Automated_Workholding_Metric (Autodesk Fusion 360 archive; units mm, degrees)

design "Automated_Workholding_Start_Metric" references "Broached Hexagon Socket Head Cap Screw ANSI B18.3.1M - M12x1.75 x 60 Steel Grade 2 Plain", "autodesk 5ax table ac head xyz"
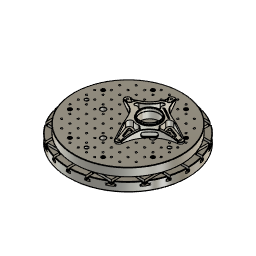
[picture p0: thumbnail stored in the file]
part number: Configuration 1
description: Part Number
part number: Hub
part number: Hub Stock
parameter "d185" = 0
base_feature "Base Feature1" bodies "c_axis_table"
sketch "Sketch1" plane through (0, 0, -15.5) normal (0, 0, -1) x axis (1, 0, 0)
  line L1 (93, 7) -> (59.5903, 7)
  line L2 (93, 93) -> (93, 7)
  line L3 (7, 93) -> (93, 93)
  line L4 (7, 59.5903) -> (7, 93)
  line L5 (12, 88) -> (12, 58.7878)
  line L6 (88, 88) -> (12, 88)
  line L7 (88, 12) -> (88, 88)
  line L8 (58.7878, 12) -> (88, 12)
  line L9 (293, -93) -> (293, -107)
  line L10 (256.1738, -100) -> (293, -100)
  arc A1 centre (0, 0) radius 60 clockwise from (58.7878, 12) to (59.5903, 7)
  arc A2 centre (0, 0) radius 60 clockwise from (7, 59.5903) to (12, 58.7878)
  circle C1 centre (0, 0) radius 275
  point P14 (293, -107)
  point P16 (293, -107)
  point P15 (293, -93)
  point P17 (293, -93)
  point P18 (293, -100)
  point P19 (256.1738, -100)
  point P20 (256.1738, -100)
  concentric A1 C1
  coincident P14 P16
  coincident P15 P17
  midpoint L9 P18
  coincident C1 P19
  perpendicular L9 L10
  coincident P19 P20
  dimension "d1" diameter C1 = 550
  dimension "d181" alignAngle = 0
  dimension "d182" alignOffsetX = 0
  dimension "d183" alignOffsetY = 0
  dimension "d184" alignOffsetZ = 0
  dimension "d185" alignAngle = 0
  dimension "d186" alignOffsetX = 0
  dimension "d187" alignOffsetY = 0
  dimension "d188" alignOffsetZ = 0
  dimension "d189" alignAngle = 0
  dimension "d190" alignOffsetX = 0
  dimension "d191" alignOffsetY = 0
  dimension "d192" alignOffsetZ = 0
  dimension "d193" alignAngle = 0
  dimension "d194" alignOffsetX = 0
  dimension "d195" alignOffsetY = 0
  dimension "d196" alignOffsetZ = 0
  dimension "d197" alignAngle = 0
  dimension "d198" alignOffsetX = 0
  dimension "d199" alignOffsetY = 0
  dimension "d200" alignOffsetZ = 0
  dimension "d201" alignAngle = 0
  dimension "d202" alignOffsetX = 0
  dimension "d203" alignOffsetY = 0
  dimension "d204" alignOffsetZ = 0
  dimension "d205" alignAngle = 0
  dimension "d206" alignOffsetX = 0
  dimension "d207" alignOffsetY = 0
  dimension "d208" alignOffsetZ = 0
  dimension "d209" alignAngle = 0
  dimension "d210" alignOffsetX = 0
  dimension "d211" alignOffsetY = 0
  dimension "d212" alignOffsetZ = 0
as_built_joint "As-built1"
work_plane "WorkPlane1"
sketch "Sketch1" plane through (256.1738, 100, -15.5) normal (-1, 0, 0) x axis (0, -1, 0)
  line L1 (0, 5) -> (0, -9)
  line L2 (7, 5) -> (0, 5)
  line L3 (11, -9) -> (0, -9)
  line L4 (11, 0) -> (11, -9)
  line L5 (7, 0) -> (11, 0)
  line L6 (7, 5) -> (7, 0)
  line L7 (-7, 5) -> (0, 5)
  line L8 (-7, 5) -> (-7, 0)
  line L9 (-7, 0) -> (-11, 0)
  line L10 (-11, 0) -> (-11, -9)
  line L11 (-11, -9) -> (0, -9)
  point P5 (0, 0)
  point P9 (7, 0)
  point P2 (0, -9)
  point P15 (0, -9)
  point P3 (0, 5)
  point P10 (0, 5)
  point P4 (7, 5)
  point P11 (-7, 5)
  point P6 (11, -9)
  point P14 (-11, -9)
  point P7 (11, 0)
  point P13 (-11, 0)
  point P8 (7, 0)
  point P12 (-7, 0)
  vertical L1
  perpendicular L1 L2
  coincident L1 P5
  perpendicular L1 L3
  perpendicular L3 L4
  perpendicular L1 L5
  perpendicular L2 L6
  coincident L5 P9
  symmetric P2 L1 P15
  symmetric P3 L1 P10
  symmetric L1 P4 P11
  symmetric L1 P6 P14
  symmetric L1 P7 P13
  symmetric L1 P8 P12
  dimension "d4" distance L1 P4 = 7 (= "( 14 / 2 ) * 1 mm")
  dimension "d5" distance P2 P3 = 14
  dimension "d6" distance P2 P6 = 11 (= "( 22 / 2 ) * 1 mm")
  dimension "d7" distance P6 P7 = 9
extrude "Extrude1" new body sketch "Sketch1" profile of L2 L3 L4 L5 L6 L7 L8 L9 L10 L11 distance 29
hole "Hole1" HoleDiameter 10.274 TipAngle 118
chamfer "Chamfer1" distance 3 distance 1
as_built_joint "As-built1"
mirror_component "MirrorComponent1"
derived_instance "DerivedInstance1"
as_built_joint "As-built2"
step "00000000-0000-0000-0000-000000000000" TotalAngle 360
work_plane "WorkPlane1" AlongDistance 20
sketch "Sketch1" plane through (0, 0, 20) normal (0, 0, 1) x axis (1, 0, 0)
  line L1 (0, 66.3083) -> (0, 0)
  circle C1 centre (100, -256.1738) radius 5.1368
  circle C2 centre (256.1738, -100) radius 5.1368
  circle C3 centre (256.1738, 100) radius 5.1368
  circle C4 centre (100, 256.1738) radius 5.1368
  circle C5 centre (-100, 256.1738) radius 5.1368
  circle C6 centre (-256.1738, 100) radius 5.1368
  circle C7 centre (-256.1738, -100) radius 5.1368
  circle C8 centre (-100, -256.1738) radius 5.1368
  point P1 (0, 0)
  point P3 (0, 0)
  coincident P1 P3
  vertical L1
sketch "Sketch1" plane through (0, 0, 0) normal (0, 0, 1) x axis (-1, 0, 0)
  line L1 (-7, 193) -> (-7, 107)
  line L2 (-93, 193) -> (-7, 193)
  line L3 (-93, 107) -> (-93, 193)
  line L4 (-7, 107) -> (-93, 107)
  circle C1 centre (0, 0) radius 325
  point P1 (0, 0)
  point P6 (0, 0)
  coincident P1 P6
  dimension "d91" diameter C1 = 650
extrude "Extrude1" new body sketch "Sketch1" along normal blind 50
sketch "Sketch2" plane through (0, 0, 50) normal (0, 0, 1) x axis (-1, 0, 0)
  line L1 (7, -207) -> (7, -293)
  line L2 (-7, -293) -> (-7, -207)
  line L3 (-7, -250) -> (7, -250)
  line L4 (-25, -25) -> (25, -25)
  line L5 (-25, 25) -> (-25, -25)
  line L6 (25, 25) -> (-25, 25)
  line L7 (25, -25) -> (25, 25)
  line L8 (-25, 25) -> (25, -25)
  line L9 (25, 25) -> (-25, -25)
  circle C1 centre (0, 0) radius 325
  point P7 (7, -250)
  point P8 (-7, -250)
  point P9 (0, -250)
  point P14 (0, 0)
  point P2 (0, 0)
  point P12 (-25, 25)
  point P13 (25, 25)
  point P11 (-25, -25)
  midpoint L1 P7
  midpoint L2 P8
  midpoint L3 P9
  horizontal L4
  perpendicular L4 L5
  parallel L4 L6
  parallel L5 L7
  coincident L8 P14
  coincident L9 P14
  coincident P2 P14
  dimension "d152" distance P12 P13 = 50
  dimension "d153" distance P11 P12 = 50
hole "Hole1" HoleDiameter 13 TipAngle 118 CBDepth 12 CBDiameter 20
rectangular_pattern "R-Pattern1" uSpaceDistance 100 vSpaceDistance 0
circular_pattern "C-Pattern1" TotalAngle 360
as_built_joint "As-built2"
step "Screw1"
joint "Assemble1" alignAngle 0 alignOffsetX 0 alignOffsetY 0 alignOffsetZ 0
step "Screw2"
joint "Assemble2" alignAngle 0 alignOffsetX 0 alignOffsetY 0 alignOffsetZ 0
step "Screw4"
joint "Assemble4" alignAngle 0 alignOffsetX 0 alignOffsetY 0 alignOffsetZ 0
step "Screw6"
joint "Assemble6" alignAngle 0 alignOffsetX 0 alignOffsetY 0 alignOffsetZ 0
step "Screw7"
joint "Assemble7" alignAngle 0 alignOffsetX 0 alignOffsetY 0 alignOffsetZ 0
step "Screw9"
joint "Assemble9" alignAngle 0 alignOffsetX 0 alignOffsetY 0 alignOffsetZ 0
step "Screw10"
joint "Assemble10" alignAngle 0 alignOffsetX 0 alignOffsetY 0 alignOffsetZ 0
step "Screw12"
joint "Assemble12" alignAngle 0 alignOffsetX 0 alignOffsetY 0 alignOffsetZ 0
hole "Hole2" HoleDepth 106.5 HoleDiameter 10.274 TipAngle 118
rectangular_pattern "R-Pattern2" countU 12 CountV 12 uSpaceDistance 50 vSpaceDistance 50
hole "Hole3" HoleDiameter 30 TipAngle 180
rectangular_pattern "R-Pattern3" uSpaceDistance 150 vSpaceDistance 150
chamfer "Chamfer1" distance 1 distance 2
base_feature "Base Feature1" bodies "Model"
position "Position2"
joint "Assemble21" alignAngle 45 named "Angle" alignOffsetX 80 named "X_Offset" alignOffsetY 50 named "Y_Offset" alignOffsetZ 0 named "Height"
base_feature "Base Feature1"
joint "Assemble22" alignAngle 0 alignOffsetX 0 alignOffsetY 0 alignOffsetZ 0
copy_paste_bodies "CutPasteBodies"
remove_instance "RemoveInstance1"
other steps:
derived_base_feature "Derived Base Feature"
base_feature "Base Feature3" bodies "Stock"
thread "Thread1" ThreadOffset 0 ThreadDepth 7.4
thread "Thread1" ThreadOffset 0 ThreadDepth 7.4
create_component "CreateComponent1"
create_component "CreateComponent1"
create_component "CreateComponent2"
create_component "CreateComponent2"
joint_origin "JointOrigin1"
joint_origin "JointOrigin2"
joint_origin "JointOrigin4"
joint_origin "JointOrigin6"
joint_origin "JointOrigin7"
joint_origin "JointOrigin9"
joint_origin "JointOrigin10"
joint_origin "JointOrigin12"
create_component "CreateComponent4"
create_component "CreateComponent5"
joint_origin "JointOrigin1"
joint_origin "JointOrigin13"
joint_origin "JointOrigin2"
create_component "CreateComponent7"
remove_body "RemoveBody1"
named bodies: "c_axis_table", "Model", "Stock"

design "Broached Hexagon Socket Head Cap Screw ANSI B18.3.1M - M12x1.75 x 60 Steel Grade 2 Plain"
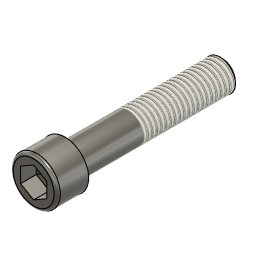
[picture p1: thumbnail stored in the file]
description: Broached Hexagon Socket Head Cap Screw ANSI B18.3.1M - M12x1.75 x 60
part number: arrangementsContainer
parameter "adsk_nomlen" = 60
parameter "adsk_headh" = 12
parameter "adsk_headdia" = 18
parameter "adsk_nomdia" = 12
parameter "adsk_philwidth" = 10
parameter "adsk_phildepth" = 6
parameter "adsk_thrlen" = 36
parameter "adsk_startlen" = 1.0735
parameter "adsk_endpointdia" = 9.8529
sketch "Sketch1" plane through (0, 0, 0) normal (0, 1, 0) x axis (1, 0, 0)
  line L1 (-6, 60) -> (-6, 0)
  line L2 (0, 60) -> (-6, 60)
  line L3 (0, -12) -> (0, 60)
  line L4 (-9, 0) -> (-6, 0)
  line L5 (-9, -12) -> (-9, 0)
  line L6 (0, -12) -> (-9, -12)
  point P1 (0, 0)
  point P4 (0, 60)
  point P7 (0, -12)
  point P5 (-9, 0)
  point P6 (-9, -12)
  perpendicular L1 L2
  collinear P1 P4 P7
  perpendicular L1 L4
  coincident P1 L4
  vertical L1
  vertical L3
  parallel L3 L5
  coincident L3 P7
  perpendicular L3 L6
  dimension "d9" = 12 (= "adsk_nomdia")
  dimension "d66" = 18 (= "adsk_headdia")
  dimension "d68" distance P1 P4 = 60 (= "adsk_nomlen")
  dimension "d79" distance P5 P6 = 12 (= "adsk_headh")
revolve "Revolve1" sketch "Sketch1" AlongAngle 360
work_plane "WorkPlane1" AlongDistance 12 (= "adsk_headh")
sketch "Sketch6" plane through (0, 0, 12) normal (0, 0, 1) x axis (1, 0, 0)
  line L1 (5, 0) -> (-5, 0)
  line L2 (-5, 2.8868) -> (0, 0)
  line L3 (-5, 2.8868) -> (-5, -2.8868)
  line L4 (0, 0) -> (-5, -2.8868)
  point P1 (0, 0)
  point P4 (0, 0)
  point P2 (-5, 0)
  point P5 (-5, 2.8868)
  point P7 (-5, 2.8868)
  point P8 (0, 0)
  point P3 (5, 0)
  horizontal L1
  midpoint P1 L1
  coincident P1 P4
  perpendicular L1 L3
  midpoint P2 L3
  coincident P5 P7
  coincident P1 P8
  dimension "d72" distance P2 P3 = 10 (= "adsk_philwidth")
  dimension "d100" angle L1 L2 = 150
extrude "Extrude1" cut sketch "Sketch6" profile of L2 L3 L4 no distance stored
circular_pattern "C-Pattern1" TotalAngle 360
extrude "Extrude2" cut of existing geometry no distance stored taper -85
thread "Thread2" ThreadOffset 0 ThreadLength 36 (= "adsk_thrlen")
fillet "Fillet4" radius 1.2 (= "adsk_nomdia * 0.1")
sketch "Sketch7" plane through (0, 0, 0) normal (0, 1, 0) x axis (1, 0, 0)
  line L1 (-6.12, 58.9265) -> (-6.12, 60)
  line L2 (-4.9265, 60) -> (-6.12, 58.9265)
  line L3 (0, -12) -> (0, 60)
  line L4 (0, 60) -> (-6.12, 60)
  point P5 (0, 60)
  point P7 (0, 60)
  point P4 (-4.9265, 60)
  point P3 (-6.12, 58.9265)
  point P1 (0, 0)
  coincident P5 P7
  perpendicular L3 L4
  coincident P4 L4
  perpendicular L1 L4
  dimension "d92" distance P3 P4 = 1.0735 (= "adsk_startlen")
  dimension "d98" distance P1 P4 = 4.9265 (= "adsk_endpointdia / 2")
  dimension "d99" distance P1 L1 = 6.12 (= "adsk_nomdia * 0.51")
revolve "Revolve3" sketch "Sketch7" AlongAngle 360
joint_origin "JointOrigin2" OffsetX 0 OffsetY 0 OffsetZ 0 AngleZ 0

design "autodesk 5ax table ac head xyz"
named bodies: "base", "a_axis_table", "c_axis_table", "y_axis_head", "x_axis_head", "z_axis_cover", "z_axis_head"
